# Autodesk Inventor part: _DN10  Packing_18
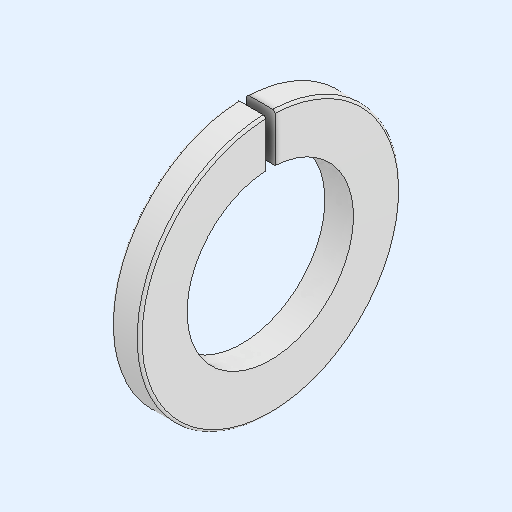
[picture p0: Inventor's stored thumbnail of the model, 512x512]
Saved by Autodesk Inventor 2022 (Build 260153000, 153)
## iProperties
Created: 2021-12
Part Number: _DN10  Packing_18
Material: Generico
Document SubType Name: Modeling
Designer: admin
Density: 1 g/cm^3
Appearance: Default
Author: admin
Revision Number: NONE
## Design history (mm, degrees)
feature "_DN10  Packing"
node "Solido1"
